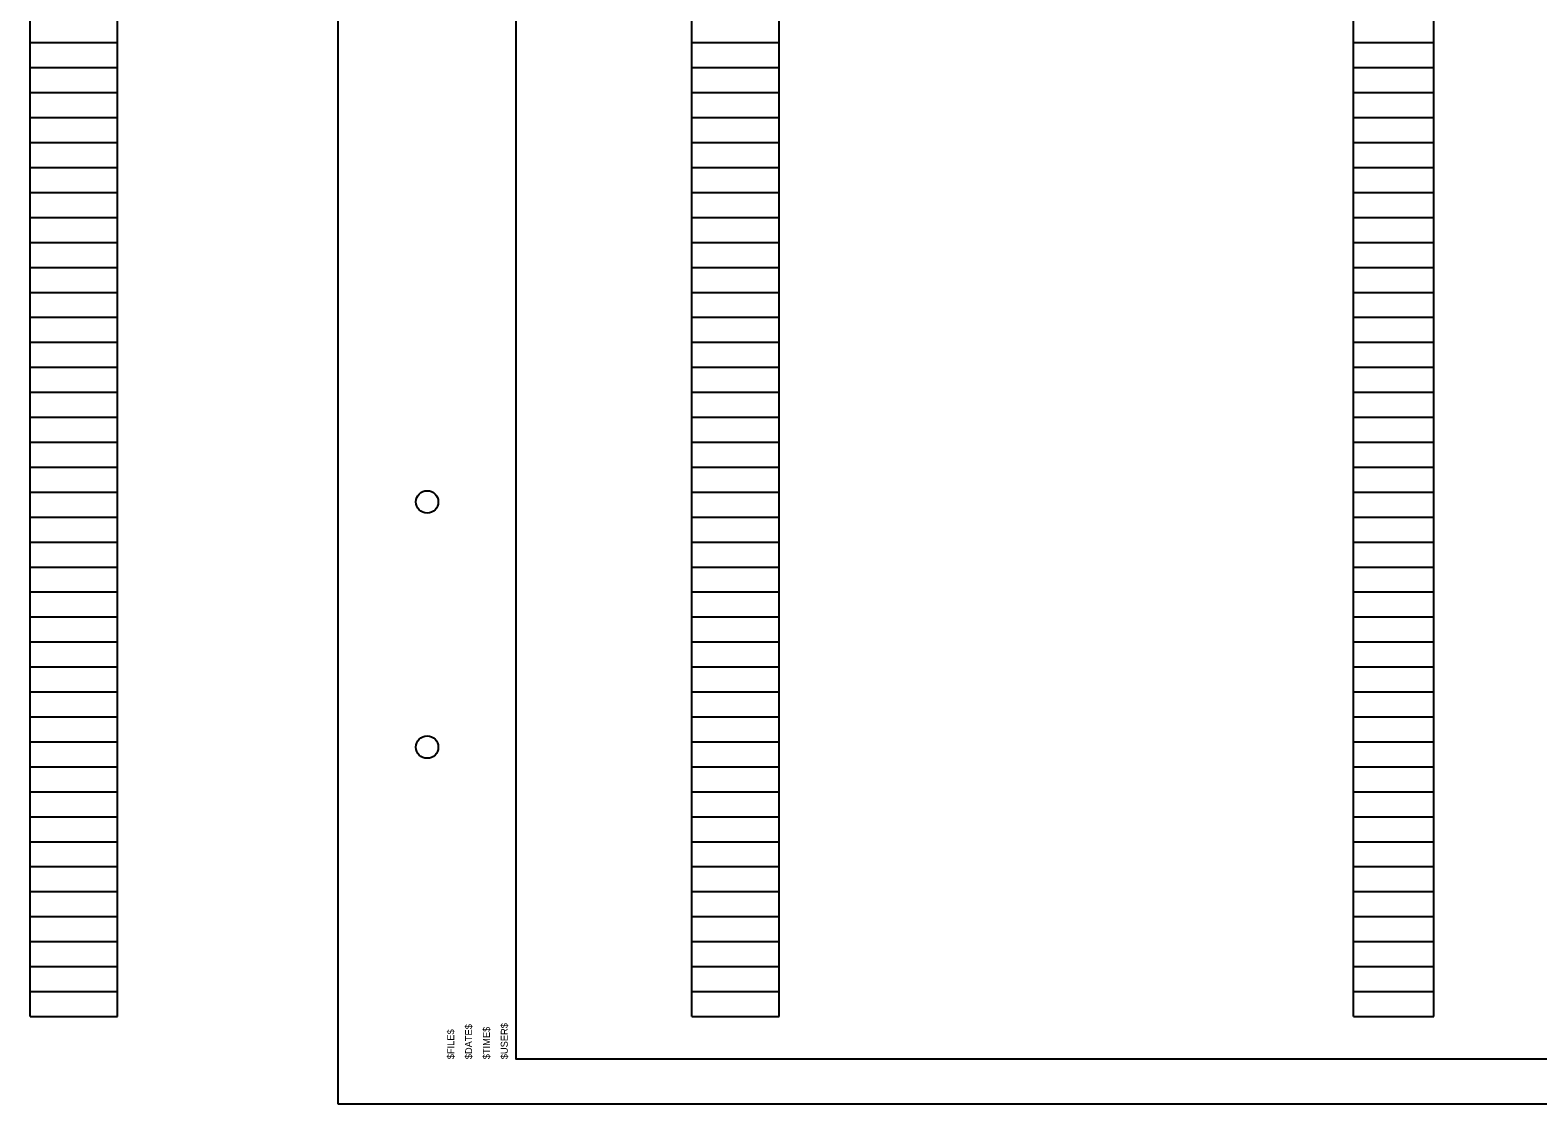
# Model space of a CAD drawing. Extents: x 30 to 362, y -13 to 11.
# Drawn here: x 86.05 to 102.96, y -12.91 to -0.87 of the extents above; entities that cross this region are included whole.
import ezdxf

# ---------------------------------------------------------------- set-up
doc = ezdxf.new("R2010")
doc.units = 0
for name, color, linetype in [('SH_Border', 7, 'Continuous'), ('SH_Cut_Line', 7, 'Continuous'), ('SH_Data', 7, 'Continuous'), ('TX_P_Misc', 7, 'Continuous')]:
    doc.layers.add(name, color=color, linetype=linetype)

msp = doc.modelspace()

# ---------------------------------------------------------------- linework, layer by layer
at = {"layer": 'SH_Border'}
msp.add_lwpolyline([(91.502, 8.593), (123.002, 8.593), (123.002, -12.407), (91.502, -12.407)], close=True, dxfattribs=at)
for centre in [(90.502, -6.157), (90.502, -8.907)]:
    msp.add_circle(centre, 0.125, dxfattribs=at)
at = {"layer": 'SH_Cut_Line'}
msp.add_lwpolyline([(89.502, -12.907), (123.502, -12.907), (123.502, 9.093), (89.502, 9.093)], close=True, dxfattribs=at)
at = {"layer": 'SH_Data'}
for p, q in [((86.05, -11.927), (86.05, 8.233)), ((87.03, -11.927), (87.03, 8.233)), ((93.47, -11.927), (93.47, 8.233)), ((94.45, -11.927), (94.45, 8.233)), ((100.89, -11.927), (100.89, 8.233)), ((101.79, -11.927), (101.79, 8.233)), ((86.05, -1.007), (87.03, -1.007)), ((93.47, -1.007), (94.45, -1.007)), ((100.89, -1.007), (101.79, -1.007)), ((86.05, -1.287), (87.03, -1.287)), ((93.47, -1.287), (94.45, -1.287)), ((100.89, -1.287), (101.79, -1.287)), ((86.05, -1.567), (87.03, -1.567)), ((93.47, -1.567), (94.45, -1.567)), ((100.89, -1.567), (101.79, -1.567)), ((86.05, -1.847), (87.03, -1.847)), ((93.47, -1.847), (94.45, -1.847)), ((100.89, -1.847), (101.79, -1.847)), ((86.05, -2.127), (87.03, -2.127)), ((93.47, -2.127), (94.45, -2.127)), ((100.89, -2.127), (101.79, -2.127)), ((86.05, -2.407), (87.03, -2.407)), ((93.47, -2.407), (94.45, -2.407)), ((100.89, -2.407), (101.79, -2.407)), ((86.05, -2.687), (87.03, -2.687)), ((93.47, -2.687), (94.45, -2.687)), ((100.89, -2.687), (101.79, -2.687)), ((86.05, -2.967), (87.03, -2.967)), ((93.47, -2.967), (94.45, -2.967)), ((100.89, -2.967), (101.79, -2.967)), ((86.05, -3.247), (87.03, -3.247)), ((93.47, -3.247), (94.45, -3.247)), ((100.89, -3.247), (101.79, -3.247)), ((86.05, -3.527), (87.03, -3.527)), ((93.47, -3.527), (94.45, -3.527)), ((100.89, -3.527), (101.79, -3.527)), ((86.05, -3.807), (87.03, -3.807)), ((93.47, -3.807), (94.45, -3.807)), ((100.89, -3.807), (101.79, -3.807)), ((86.05, -4.087), (87.03, -4.087)), ((93.47, -4.087), (94.45, -4.087)), ((100.89, -4.087), (101.79, -4.087)), ((86.05, -4.367), (87.03, -4.367)), ((93.47, -4.367), (94.45, -4.367)), ((100.89, -4.367), (101.79, -4.367)), ((86.05, -4.647), (87.03, -4.647)), ((93.47, -4.647), (94.45, -4.647)), ((100.89, -4.647), (101.79, -4.647)), ((86.05, -4.927), (87.03, -4.927)), ((93.47, -4.927), (94.45, -4.927)), ((100.89, -4.927), (101.79, -4.927)), ((86.05, -5.207), (87.03, -5.207)), ((93.47, -5.207), (94.45, -5.207)), ((100.89, -5.207), (101.79, -5.207)), ((86.05, -5.487), (87.03, -5.487)), ((93.47, -5.487), (94.45, -5.487)), ((100.89, -5.487), (101.79, -5.487)), ((86.05, -5.767), (87.03, -5.767)), ((93.47, -5.767), (94.45, -5.767)), ((100.89, -5.767), (101.79, -5.767)), ((86.05, -6.047), (87.03, -6.047)), ((93.47, -6.047), (94.45, -6.047)), ((100.89, -6.047), (101.79, -6.047)), ((86.05, -6.327), (87.03, -6.327)), ((93.47, -6.327), (94.45, -6.327)), ((100.89, -6.327), (101.79, -6.327)), ((86.05, -6.607), (87.03, -6.607)), ((93.47, -6.607), (94.45, -6.607)), ((100.89, -6.607), (101.79, -6.607)), ((86.05, -6.887), (87.03, -6.887)), ((93.47, -6.887), (94.45, -6.887)), ((100.89, -6.887), (101.79, -6.887)), ((86.05, -7.167), (87.03, -7.167)), ((93.47, -7.167), (94.45, -7.167)), ((100.89, -7.167), (101.79, -7.167)), ((86.05, -7.447), (87.03, -7.447)), ((93.47, -7.447), (94.45, -7.447)), ((100.89, -7.447), (101.79, -7.447)), ((86.05, -7.727), (87.03, -7.727)), ((93.47, -7.727), (94.45, -7.727)), ((100.89, -7.727), (101.79, -7.727)), ((86.05, -8.007), (87.03, -8.007)), ((93.47, -8.007), (94.45, -8.007)), ((100.89, -8.007), (101.79, -8.007)), ((86.05, -8.287), (87.03, -8.287)), ((93.47, -8.287), (94.45, -8.287)), ((100.89, -8.287), (101.79, -8.287)), ((86.05, -8.567), (87.03, -8.567)), ((93.47, -8.567), (94.45, -8.567)), ((100.89, -8.567), (101.79, -8.567)), ((86.05, -8.847), (87.03, -8.847)), ((93.47, -8.847), (94.45, -8.847)), ((100.89, -8.847), (101.79, -8.847)), ((86.05, -9.127), (87.03, -9.127)), ((93.47, -9.127), (94.45, -9.127)), ((100.89, -9.127), (101.79, -9.127)), ((86.05, -9.407), (87.03, -9.407)), ((93.47, -9.407), (94.45, -9.407)), ((100.89, -9.407), (101.79, -9.407)), ((86.05, -9.687), (87.03, -9.687)), ((93.47, -9.687), (94.45, -9.687)), ((100.89, -9.687), (101.79, -9.687)), ((86.05, -9.967), (87.03, -9.967)), ((93.47, -9.967), (94.45, -9.967)), ((100.89, -9.967), (101.79, -9.967)), ((86.05, -10.247), (87.03, -10.247)), ((93.47, -10.247), (94.45, -10.247)), ((100.89, -10.247), (101.79, -10.247)), ((86.05, -10.527), (87.03, -10.527)), ((93.47, -10.527), (94.45, -10.527)), ((100.89, -10.527), (101.79, -10.527)), ((86.05, -10.807), (87.03, -10.807)), ((93.47, -10.807), (94.45, -10.807)), ((100.89, -10.807), (101.79, -10.807)), ((86.05, -11.087), (87.03, -11.087)), ((93.47, -11.087), (94.45, -11.087)), ((100.89, -11.087), (101.79, -11.087)), ((86.05, -11.367), (87.03, -11.367)), ((93.47, -11.367), (94.45, -11.367)), ((100.89, -11.367), (101.79, -11.367)), ((86.05, -11.647), (87.03, -11.647)), ((93.47, -11.647), (94.45, -11.647)), ((100.89, -11.647), (101.79, -11.647)), ((86.05, -11.927), (87.03, -11.927)), ((93.47, -11.927), (94.45, -11.927)), ((100.89, -11.927), (101.79, -11.927))]:
    msp.add_line(p, q, dxfattribs=at)

# ---------------------------------------------------------------- texts
at = {"layer": 'TX_P_Misc'}
for s, p in [('$USER$', (91.406, -12.407)), ('$FILE$', (90.806, -12.407)), ('$DATE$', (91.006, -12.407)), ('$TIME$', (91.206, -12.407))]:
    msp.add_text(s, height=0.078, rotation=90, dxfattribs=at).set_placement(p)

doc.saveas('drawing.dxf')
